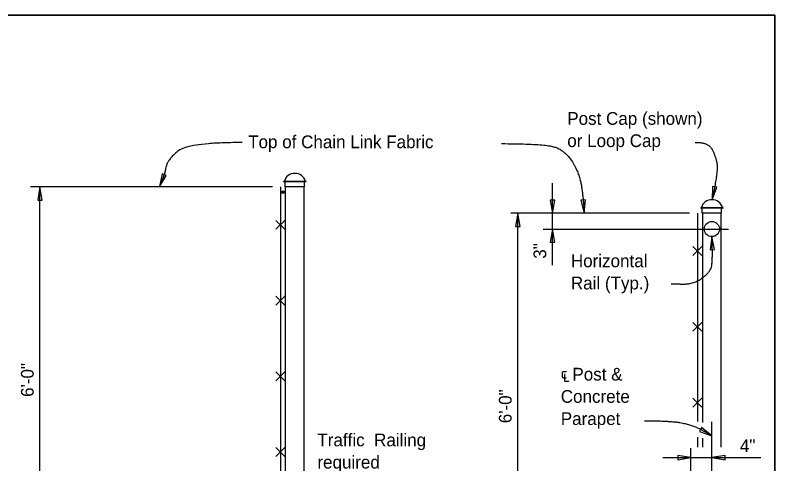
# Model space of a CAD drawing. Extents: x 0 to 41.1, y 0 to 25.9.
# Drawn here: x 29.01 to 41.05, y 18.84 to 25.95 of the extents above; entities that cross this region are included whole.
import ezdxf

# ---------------------------------------------------------------- set-up
doc = ezdxf.new("R2010")
doc.units = 0
for name, color, linetype in [('ActivePts-ConstElements', 7, 'Continuous'), ('CL_Major', 7, 'Continuous'), ('Dimension', 7, 'Continuous'), ('Miscellaneous', 7, 'Continuous'), ('Miscellaneous1', 7, 'Continuous'), ('SteelMisc', 7, 'Continuous'), ('TextStructures', 7, 'Continuous')]:
    doc.layers.add(name, color=color, linetype=linetype)

msp = doc.modelspace()

# ---------------------------------------------------------------- linework, layer by layer
at = {"layer": 'ActivePts-ConstElements'}
msp.add_lwpolyline([(0, 0), (41.051, 0), (41.051, 25.946), (0, 25.946)], close=True, dxfattribs=at)
at = {"layer": 'CL_Major'}
for p, q in [((37.378, 22.558), (40.319, 22.558)), ((40.054, 15.283), (40.054, 19.502))]:
    msp.add_line(p, q, dxfattribs=at)
at = {"layer": 'Dimension'}
for p, q in [((37.528, 21.984), (37.528, 23.282)), ((33.092, 23.225), (29.256, 23.225)), ((29.406, 14.225), (29.406, 23.225)), ((39.699, 22.808), (36.866, 22.808)), ((36.98, 14.225), (36.98, 22.808)), ((39.72, 16.64), (39.72, 19.086)), ((39.274, 18.936), (40.828, 18.936))]:
    msp.add_line(p, q, dxfattribs=at)
for points in [[(31.3, 23.225), (31.408, 23.406), (31.342, 23.432)], [(40.057, 23.023), (40.131, 23.22), (40.062, 23.234)], [(29.406, 23.225), (29.371, 23.016), (29.441, 23.016)], [(37.528, 22.808), (37.563, 23.016), (37.492, 23.016)], [(38.031, 22.808), (38.049, 23.018), (37.979, 23.013)], [(36.98, 22.808), (36.944, 22.6), (37.015, 22.6)], [(37.528, 22.558), (37.492, 22.35), (37.563, 22.35)], [(40.054, 22.438), (40.024, 22.229), (40.095, 22.231)], [(40.054, 19.28), (39.889, 19.412), (39.855, 19.35)], [(39.72, 18.936), (39.512, 18.971), (39.512, 18.901)], [(40.054, 18.936), (40.262, 18.901), (40.262, 18.971)]]:
    msp.add_lwpolyline(points, close=True, dxfattribs=at)
for points in [[(32.608, 23.928), (31.76, 23.928), (31.424, 23.657), (31.383, 23.422), (31.3, 23.225)], [(36.717, 23.911), (37.4, 23.911), (37.736, 23.799), (37.958, 23.427), (38.014, 23.066), (38.031, 22.808)], [(39.786, 23.927), (39.992, 23.942), (40.118, 23.698), (40.152, 23.473), (40.057, 23.023)], [(39.41, 21.689), (39.436, 21.689), (39.754, 21.683), (40.017, 21.86), (40.072, 22.038), (40.054, 22.438)], [(38.988, 19.52), (39.396, 19.52), (39.727, 19.457), (39.975, 19.335), (40.054, 19.28)]]:
    msp.add_open_spline(points, degree=2, dxfattribs=at)
at = {"layer": 'Miscellaneous'}
for p, q in [((33.286, 22.695), (33.145, 22.554)), ((33.145, 22.695), (33.286, 22.554)), ((39.895, 22.279), (39.754, 22.137)), ((39.754, 22.279), (39.895, 22.137)), ((33.286, 21.495), (33.145, 21.354)), ((33.145, 21.495), (33.286, 21.354)), ((39.895, 21.079), (39.754, 20.937)), ((39.754, 21.079), (39.895, 20.937)), ((33.286, 20.295), (33.145, 20.154)), ((33.145, 20.295), (33.286, 20.154)), ((39.895, 19.879), (39.754, 19.737)), ((39.754, 19.879), (39.895, 19.737)), ((33.286, 19.095), (33.145, 18.954)), ((33.145, 19.095), (33.286, 18.954))]:
    msp.add_line(p, q, dxfattribs=at)
for points in [[(33.215, 23.225), (33.215, 17.225)], [(39.825, 22.808), (39.825, 19.51)], [(39.825, 19.262), (39.825, 19.1)]]:
    msp.add_lwpolyline(points, dxfattribs=at)
at = {"layer": 'Miscellaneous1'}
msp.add_lwpolyline([(0, 25.946), (41.051, 25.946), (41.051, 0), (0, 0)], close=True, dxfattribs=at)
at = {"layer": 'SteelMisc'}
for p, q in [((33.272, 23.317), (33.617, 23.317)), ((33.617, 23.304), (33.272, 23.304)), ((33.291, 23.225), (33.291, 23.304)), ((33.599, 23.225), (33.599, 23.304)), ((33.215, 23.225), (33.215, 17.225)), ((33.599, 23.225), (33.291, 23.225)), ((33.299, 16.889), (33.299, 23.225)), ((33.59, 16.889), (33.59, 23.225)), ((39.881, 22.9), (40.226, 22.9)), ((40.226, 22.888), (39.881, 22.888)), ((39.9, 22.808), (39.9, 22.888)), ((40.208, 22.808), (40.208, 22.888)), ((40.208, 22.808), (39.9, 22.808)), ((39.908, 19.495), (39.908, 22.808)), ((40.2, 19.1), (40.2, 22.808)), ((39.908, 19.1), (39.908, 19.244))]:
    msp.add_line(p, q, dxfattribs=at)
for centre, radius in [((33.257, 23.141), 0.0197), ((33.257, 23.141), 0.0172), ((33.257, 23.141), 0.0147), ((33.257, 23.141), 0.0122), ((33.257, 23.141), 0.00975), ((33.257, 23.141), 0.00725), ((33.257, 23.141), 0.00475), ((33.257, 23.141), 0.00225), ((40.054, 22.558), 0.12)]:
    msp.add_circle(centre, radius, dxfattribs=at)
for centre, start, end in [((33.272, 23.31), 91.1647, 268.8353), ((33.617, 23.31), 271.1647, 88.8353), ((39.882, 22.894), 91.1647, 268.8353), ((40.226, 22.894), 271.1647, 88.8353)]:
    msp.add_arc(centre, 0.00613, start, end, dxfattribs=at)
for centre in [(33.445, 23.276), (40.054, 22.859)]:
    msp.add_ellipse(centre, major_axis=(0.171, 0), ratio=0.957868, start_param=0.252602, end_param=2.888574, dxfattribs=at)

# ---------------------------------------------------------------- texts
at = {"layer": 'Dimension'}
for s, p in [('Post Cap (shown) ', (37.762, 24.209)), ('or Loop Cap', (37.762, 23.857)), ('Horizontal', (37.819, 21.953)), ('Rail (Typ.)', (37.819, 21.601)), ('℄ Post &', (37.659, 20.157)), ('Concrete', (37.659, 19.805)), ('Parapet', (37.659, 19.453)), ('Traffic  Railing', (33.802, 19.115)), ('required', (33.802, 18.763))]:
    msp.add_text(s, height=0.2016, dxfattribs=at).set_placement(p)
at = {"layer": 'TextStructures'}
for s, p in [('Top of Chain Link Fabric', (32.705, 23.839)), ('4"', (40.497, 19.023))]:
    msp.add_text(s, height=0.2016, dxfattribs=at).set_placement(p)
for s, p in [('3"', (37.428, 22.087)), ('6\'-0"', (29.306, 19.898)), ('6\'-0"', (36.88, 19.481))]:
    msp.add_text(s, height=0.2016, rotation=90, dxfattribs=at).set_placement(p)

doc.saveas('drawing.dxf')
